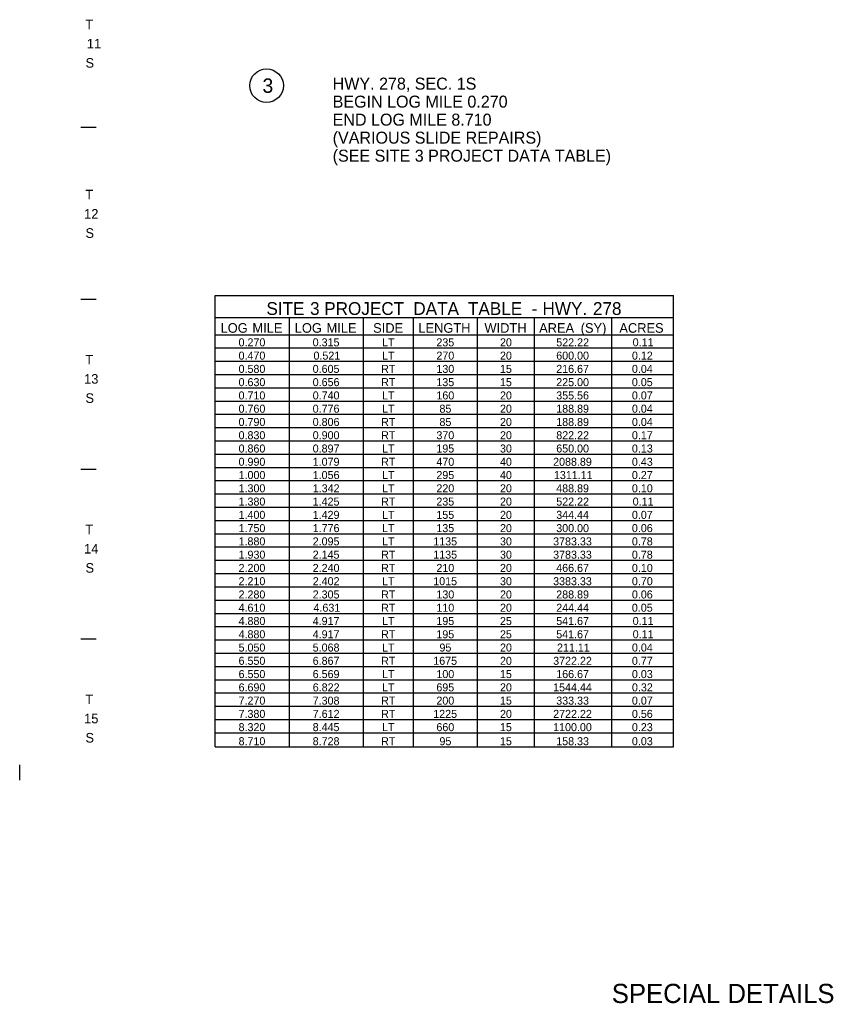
# Model space of a CAD drawing. Extents: x -42408 to 34530, y -43140 to 20491.
# Drawn here: x 11805 to 16887, y -43140 to -36997 of the extents above; entities that cross this region are included whole.
import ezdxf

# ---------------------------------------------------------------- set-up
doc = ezdxf.new("R2010")
doc.units = 0
for name, color, linetype in [('2', 7, 'Continuous'), ('30', 7, 'Continuous'), ('Default', 7, 'Continuous'), ('S_MISC_BOUNDARY', 7, 'Continuous')]:
    doc.layers.add(name, color=color, linetype=linetype)

msp = doc.modelspace()

# ---------------------------------------------------------------- linework, layer by layer
at = {"layer": '30'}
msp.add_circle((13347.2, -37408.9), 105, dxfattribs=at)
at = {"layer": 'Default'}
for p, q in [((12282, -37670.2), (12187, -37670.2)), ((12282, -38744.6), (12187, -38744.6)), ((13026.3, -38720.5), (15888, -38720.5)), ((13026.3, -41538.2), (13026.3, -38720.5)), ((15888, -41538.2), (15888, -38720.5)), ((13026.3, -38857), (15888, -38857)), ((13489.5, -41538.2), (13489.5, -38857)), ((13952.6, -41538.2), (13952.6, -38857)), ((14264.6, -41538.2), (14264.6, -38857)), ((14664.3, -41538.2), (14664.3, -38857)), ((15020.2, -41538.2), (15020.2, -38857)), ((15502.8, -41538.2), (15502.8, -38857)), ((13026.3, -38964.2), (15888, -38964.2)), ((13026.3, -38964.2), (15888, -38964.2)), ((13489.5, -41538.2), (13489.5, -38964.2)), ((14264.6, -41538.2), (14264.6, -38964.2)), ((14664.3, -41538.2), (14664.3, -38964.2)), ((15020.2, -41538.2), (15020.2, -38964.2)), ((15502.8, -41538.2), (15502.8, -38964.2)), ((13026.3, -39047.1), (15888, -39047.1)), ((13026.3, -39130), (15888, -39130)), ((13026.3, -39212.9), (15888, -39212.9)), ((13026.3, -39295.7), (15888, -39295.7)), ((13026.3, -39378.6), (15888, -39378.6)), ((13026.3, -39461.5), (15888, -39461.5)), ((13026.3, -39544.4), (15888, -39544.4)), ((13026.3, -39627.2), (15888, -39627.2)), ((13026.3, -39710.1), (15888, -39710.1)), ((12282, -39805.3), (12187, -39805.3)), ((13026.3, -39793), (15888, -39793)), ((13026.3, -39875.9), (15888, -39875.9)), ((13026.3, -39958.7), (15888, -39958.7)), ((13026.3, -40041.6), (15888, -40041.6)), ((13026.3, -40124.5), (15888, -40124.5)), ((13026.3, -40207.4), (15888, -40207.4)), ((13026.3, -40290.2), (15888, -40290.2)), ((13026.3, -40373.1), (15888, -40373.1)), ((13026.3, -40456), (15888, -40456)), ((13026.3, -40538.9), (15888, -40538.9)), ((13026.3, -40621.7), (15888, -40621.7)), ((13026.3, -40704.6), (15888, -40704.6)), ((13026.3, -40787.5), (15888, -40787.5)), ((12282, -40865.9), (12187, -40865.9)), ((13026.3, -40870.4), (15888, -40870.4)), ((13026.3, -40953.2), (15888, -40953.2)), ((13026.3, -41036.1), (15888, -41036.1)), ((13026.3, -41119), (15888, -41119)), ((13026.3, -41201.9), (15888, -41201.9)), ((13026.3, -41284.7), (15888, -41284.7)), ((13026.3, -41367.6), (15888, -41367.6)), ((13026.3, -41450.5), (15888, -41450.5)), ((13026.3, -41538.2), (15888, -41538.2)), ((11804.9, -41650.8), (11804.9, -41745.8))]:
    msp.add_line(p, q, dxfattribs=at)
at = {"layer": 'S_MISC_BOUNDARY'}
for p, q in [((13745.4, -37343.8), (13745.4, -37343.8)), ((13026.3, -38720.5), (13026.3, -38720.5))]:
    msp.add_line(p, q, dxfattribs=at)

# ---------------------------------------------------------------- texts
at = {"layer": '2'}
for s, p in [('T', (12214.9, -37056.8)), ('11', (12224.5, -37176.8)), ('S', (12216, -37296.8)), ('T', (12214.9, -38119.4)), ('12', (12207.5, -38239.4)), ('S', (12216, -38359.4)), ('T', (12214.9, -39150.3)), ('13', (12207.5, -39270.3)), ('S', (12216, -39390.3)), ('T', (12214.9, -40210.9)), ('14', (12207.5, -40330.9)), ('S', (12216, -40450.9)), ('T', (12214.9, -41271.6)), ('15', (12207.5, -41391.6)), ('S', (12216, -41511.6))]:
    msp.add_text(s, height=60, dxfattribs=at).set_placement(p)
at = {"layer": '30'}
for s, height, p in [('3', 90, (13321.7, -37453.9)), ('SPECIAL DETAILS', 120, (15503.2, -43138.6))]:
    msp.add_text(s, height=height, dxfattribs=at).set_placement(p)
at = {"layer": 'Default'}
for s, height, p in [('HWY. 278, SEC. 1S', 75, (13760, -37433.8)), ('BEGIN LOG MILE 0.270', 75, (13760, -37546.3)), ('END LOG MILE 8.710', 75, (13760, -37658.8)), ('(VARIOUS SLIDE REPAIRS)', 75, (13760, -37771.3)), ('(SEE SITE 3 PROJECT DATA TABLE)', 75, (13760, -37883.8)), ('SITE', 80, (13346.1, -38841)), (' 3', 80, (13589, -38841)), (' PROJECT', 80, (13677.3, -38841)), (' DATA', 80, (14234, -38841)), (' TABLE', 80, (14575.1, -38841)), (' HWY.', 80, (15040.6, -38841)), (' 278', 80, (15355.8, -38841)), (' -', 80, (14973.2, -38841)), ('LOG', 60, (13059.9, -38952.2)), (' MILE', 60, (13236.5, -38952.2)), ('LOG', 60, (13523.1, -38952.2)), (' MILE', 60, (13699.6, -38952.2)), ('SIDE', 60, (14012.8, -38952.2)), ('LENGTH', 60, (14295.4, -38952.2)), ('WIDTH', 60, (14708.1, -38952.2)), ('AREA', 60, (15049.6, -38952.2)), (' (SY)', 60, (15286.8, -38952.2)), ('ACRES', 60, (15550.7, -38952.2)), ('0.270', 50, (13172.2, -39037.1)), ('0.315', 50, (13635.1, -39037.1)), ('LT', 50, (14068.5, -39037.1)), ('235', 50, (14407.6, -39037.1)), ('20', 50, (14805.1, -39037.1)), ('522.22', 50, (15156.6, -39037.1)), ('0.11', 50, (15633.9, -39037.1)), ('0.470', 50, (13172.2, -39120)), ('0.521', 50, (13640.1, -39120)), ('LT', 50, (14068.5, -39120)), ('270', 50, (14407.9, -39120)), ('20', 50, (14805.1, -39120)), ('600.00', 50, (15156.4, -39120)), ('0.12', 50, (15629.3, -39120)), ('0.580', 50, (13172.2, -39202.9)), ('0.605', 50, (13635.1, -39202.9)), ('RT', 50, (14062.7, -39202.9)), ('130', 50, (14407.9, -39202.9)), ('15', 50, (14804.8, -39202.9)), ('216.67', 50, (15156.3, -39202.9)), ('0.04', 50, (15629.2, -39202.9)), ('0.630', 50, (13172.2, -39285.7)), ('0.656', 50, (13635.2, -39285.7)), ('RT', 50, (14062.7, -39285.7)), ('135', 50, (14407.6, -39285.7)), ('15', 50, (14804.8, -39285.7)), ('225.00', 50, (15156.4, -39285.7)), ('0.05', 50, (15628.8, -39285.7)), ('0.710', 50, (13172.2, -39368.6)), ('0.740', 50, (13635.3, -39368.6)), ('160', 50, (14407.9, -39368.6)), ('20', 50, (14805.1, -39368.6)), ('355.56', 50, (15156.3, -39368.6)), ('0.07', 50, (15629, -39368.6)), ('LT', 50, (14068.5, -39368.6)), ('0.760', 50, (13172.2, -39451.5)), ('0.776', 50, (13635.2, -39451.5)), ('LT', 50, (14068.5, -39451.5)), ('85', 50, (14427, -39451.5)), ('20', 50, (14805.1, -39451.5)), ('188.89', 50, (15156.3, -39451.5)), ('0.04', 50, (15629.2, -39451.5)), ('0.790', 50, (13172.2, -39534.4)), ('0.806', 50, (13635.2, -39534.4)), ('RT', 50, (14062.7, -39534.4)), ('85', 50, (14427, -39534.4)), ('20', 50, (14805.1, -39534.4)), ('188.89', 50, (15156.3, -39534.4)), ('0.04', 50, (15629.2, -39534.4)), ('0.830', 50, (13172.2, -39617.2)), ('0.900', 50, (13635.3, -39617.2)), ('RT', 50, (14062.7, -39617.2)), ('370', 50, (14407.9, -39617.2)), ('20', 50, (14805.1, -39617.2)), ('822.22', 50, (15156.6, -39617.2)), ('0.17', 50, (15629, -39617.2)), ('0.860', 50, (13172.2, -39700.1)), ('0.897', 50, (13635.2, -39700.1)), ('LT', 50, (14068.5, -39700.1)), ('195', 50, (14407.6, -39700.1)), ('30', 50, (14805.1, -39700.1)), ('650.00', 50, (15156.4, -39700.1)), ('0.13', 50, (15629, -39700.1)), ('0.990', 50, (13172.2, -39783)), ('1.079', 50, (13635.2, -39783)), ('RT', 50, (14062.7, -39783)), ('470', 50, (14407.9, -39783)), ('40', 50, (14805.1, -39783)), ('2088.89', 50, (15136.9, -39783)), ('0.43', 50, (15629, -39783)), ('1.000', 50, (13172.2, -39865.9)), ('1.056', 50, (13635.2, -39865.9)), ('LT', 50, (14068.5, -39865.9)), ('295', 50, (14407.6, -39865.9)), ('40', 50, (14805.1, -39865.9)), ('1311.11', 50, (15141.8, -39865.9)), ('0.27', 50, (15629, -39865.9)), ('1.300', 50, (13172.2, -39948.7)), ('1.342', 50, (13635.5, -39948.7)), ('LT', 50, (14068.5, -39948.7)), ('220', 50, (14407.9, -39948.7)), ('20', 50, (14805.1, -39948.7)), ('488.89', 50, (15156.3, -39948.7)), ('0.10', 50, (15629.1, -39948.7)), ('1.380', 50, (13172.2, -40031.6)), ('1.425', 50, (13635.1, -40031.6)), ('RT', 50, (14062.7, -40031.6)), ('235', 50, (14407.6, -40031.6)), ('20', 50, (14805.1, -40031.6)), ('522.22', 50, (15156.6, -40031.6)), ('0.11', 50, (15633.9, -40031.6)), ('1.400', 50, (13172.2, -40114.5)), ('1.429', 50, (13635.2, -40114.5)), ('LT', 50, (14068.5, -40114.5)), ('155', 50, (14407.6, -40114.5)), ('20', 50, (14805.1, -40114.5)), ('344.44', 50, (15156.4, -40114.5)), ('0.07', 50, (15629, -40114.5)), ('1.750', 50, (13172.2, -40197.4)), ('1.776', 50, (13635.2, -40197.4)), ('LT', 50, (14068.5, -40197.4)), ('135', 50, (14407.6, -40197.4)), ('20', 50, (14805.1, -40197.4)), ('300.00', 50, (15156.4, -40197.4)), ('0.06', 50, (15629, -40197.4)), ('1.880', 50, (13172.2, -40280.2)), ('2.095', 50, (13635.1, -40280.2)), ('LT', 50, (14068.5, -40280.2)), ('1135', 50, (14388.2, -40280.2)), ('30', 50, (14805.1, -40280.2)), ('3783.33', 50, (15136.9, -40280.2)), ('0.78', 50, (15629, -40280.2)), ('1.930', 50, (13172.2, -40363.1)), ('2.145', 50, (13635.1, -40363.1)), ('RT', 50, (14062.7, -40363.1)), ('1135', 50, (14388.2, -40363.1)), ('30', 50, (14805.1, -40363.1)), ('3783.33', 50, (15136.9, -40363.1)), ('0.78', 50, (15629, -40363.1)), ('2.200', 50, (13172.2, -40446)), ('2.240', 50, (13635.3, -40446)), ('RT', 50, (14062.7, -40446)), ('210', 50, (14407.9, -40446)), ('20', 50, (14805.1, -40446)), ('466.67', 50, (15156.3, -40446)), ('0.10', 50, (15629.1, -40446)), ('2.210', 50, (13172.2, -40528.9)), ('2.402', 50, (13635.5, -40528.9)), ('LT', 50, (14068.5, -40528.9)), ('1015', 50, (14388.2, -40528.9)), ('30', 50, (14805.1, -40528.9)), ('3383.33', 50, (15136.9, -40528.9)), ('0.70', 50, (15629.1, -40528.9)), ('2.280', 50, (13172.2, -40611.7)), ('2.305', 50, (13635.1, -40611.7)), ('RT', 50, (14062.7, -40611.7)), ('130', 50, (14407.9, -40611.7)), ('20', 50, (14805.1, -40611.7)), ('288.89', 50, (15156.3, -40611.7)), ('0.06', 50, (15629, -40611.7)), ('4.610', 50, (13172.2, -40694.6)), ('4.631', 50, (13640.1, -40694.6)), ('RT', 50, (14062.7, -40694.6)), ('110', 50, (14407.9, -40694.6)), ('20', 50, (14805.1, -40694.6)), ('244.44', 50, (15156.4, -40694.6)), ('0.05', 50, (15628.8, -40694.6)), ('4.880', 50, (13172.2, -40777.5)), ('4.917', 50, (13635.2, -40777.5)), ('LT', 50, (14068.5, -40777.5)), ('195', 50, (14407.6, -40777.5)), ('25', 50, (14804.8, -40777.5)), ('541.67', 50, (15156.3, -40777.5)), ('0.11', 50, (15633.9, -40777.5)), ('4.880', 50, (13172.2, -40860.4)), ('4.917', 50, (13635.2, -40860.4)), ('RT', 50, (14062.7, -40860.4)), ('195', 50, (14407.6, -40860.4)), ('25', 50, (14804.8, -40860.4)), ('541.67', 50, (15156.3, -40860.4)), ('0.11', 50, (15633.9, -40860.4)), ('5.050', 50, (13172.2, -40943.2)), ('5.068', 50, (13635.2, -40943.2)), ('LT', 50, (14068.5, -40943.2)), ('95', 50, (14427, -40943.2)), ('20', 50, (14805.1, -40943.2)), ('211.11', 50, (15161.2, -40943.2)), ('0.04', 50, (15629.2, -40943.2)), ('6.550', 50, (13172.2, -41026.1)), ('6.867', 50, (13635.2, -41026.1)), ('RT', 50, (14062.7, -41026.1)), ('1675', 50, (14388.2, -41026.1)), ('20', 50, (14805.1, -41026.1)), ('3722.22', 50, (15137.2, -41026.1)), ('0.77', 50, (15629, -41026.1)), ('6.550', 50, (13172.2, -41109)), ('6.569', 50, (13635.2, -41109)), ('LT', 50, (14068.5, -41109)), ('100', 50, (14407.9, -41109)), ('15', 50, (14804.8, -41109)), ('166.67', 50, (15156.3, -41109)), ('0.03', 50, (15629, -41109)), ('6.690', 50, (13172.2, -41191.9)), ('6.822', 50, (13635.5, -41191.9)), ('LT', 50, (14068.5, -41191.9)), ('695', 50, (14407.6, -41191.9)), ('20', 50, (14805.1, -41191.9)), ('1544.44', 50, (15137, -41191.9)), ('0.32', 50, (15629.3, -41191.9)), ('7.270', 50, (13172.2, -41274.7)), ('7.308', 50, (13635.2, -41274.7)), ('RT', 50, (14062.7, -41274.7)), ('200', 50, (14407.9, -41274.7)), ('15', 50, (14804.8, -41274.7)), ('333.33', 50, (15156.3, -41274.7)), ('0.07', 50, (15629, -41274.7)), ('7.380', 50, (13172.2, -41357.6)), ('7.612', 50, (13635.5, -41357.6)), ('RT', 50, (14062.7, -41357.6)), ('1225', 50, (14388.2, -41357.6)), ('20', 50, (14805.1, -41357.6)), ('2722.22', 50, (15137.2, -41357.6)), ('0.56', 50, (15629, -41357.6)), ('8.320', 50, (13172.2, -41440.5)), ('8.445', 50, (13635.1, -41440.5)), ('LT', 50, (14068.5, -41440.5)), ('660', 50, (14407.9, -41440.5)), ('15', 50, (14804.8, -41440.5)), ('1100.00', 50, (15137, -41440.5)), ('0.23', 50, (15629, -41440.5)), ('8.710', 50, (13172.2, -41528.2)), ('8.728', 50, (13635.2, -41528.2)), ('RT', 50, (14062.7, -41528.2)), ('95', 50, (14427, -41528.2)), ('15', 50, (14804.8, -41528.2)), ('158.33', 50, (15156.3, -41528.2)), ('0.03', 50, (15629, -41528.2))]:
    msp.add_text(s, height=height, dxfattribs=at).set_placement(p)

doc.saveas('drawing.dxf')
